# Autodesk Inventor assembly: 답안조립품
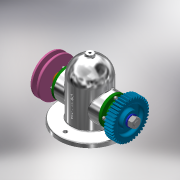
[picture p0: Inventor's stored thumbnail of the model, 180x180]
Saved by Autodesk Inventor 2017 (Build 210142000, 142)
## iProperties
Created: 2019-11
Part Number: 답안조립품
Document SubType Name: Assembly
Designer: 1-19-lg
Author: 1-19-lg
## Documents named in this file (14)
- C:\Users\1-19-lg\Desktop\491104V1003\답안조립품.iam
- C:\Users\1-19-lg\Desktop\491104V1003\본체.ipt
- C:\Users\1-19-lg\Desktop\491104V1003\부시.ipt
- C:\Users\1-19-lg\Desktop\491104V1003\스퍼기어.ipt
- C:\Users\1-19-lg\Desktop\491104V1003\오일 실 26 38 8.ipt
- C:\Users\1-19-lg\Desktop\491104V1003\와셔 12x24.ipt
- C:\Users\1-19-lg\Desktop\491104V1003\축.ipt
- C:\Users\1-19-lg\Desktop\491104V1003\커버.ipt
- C:\Users\1-19-lg\Desktop\491104V1003\키 5x5x12.ipt
- C:\Users\1-19-lg\Desktop\491104V1003\볼트 M4.ipt
- C:\Users\1-19-lg\Desktop\491104V1003\너트 M12x1.25.ipt
- C:\Users\1-19-lg\Desktop\491104V1003\베어링 6203.ipt
- C:\Users\1-19-lg\Desktop\491104V1003\V-벨트풀리.ipt
- V-벨트풀리.ipt
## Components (1 placed, 1 different names)
1. V-벨트풀리:1 — Mate:26, Mate:27, Mate:28, Mate:38
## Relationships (4: Mate 4)
- Mate:26: V-벨트풀리:1
- Mate:27: V-벨트풀리:1
- Mate:28: V-벨트풀리:1
- Mate:38: V-벨트풀리:1
